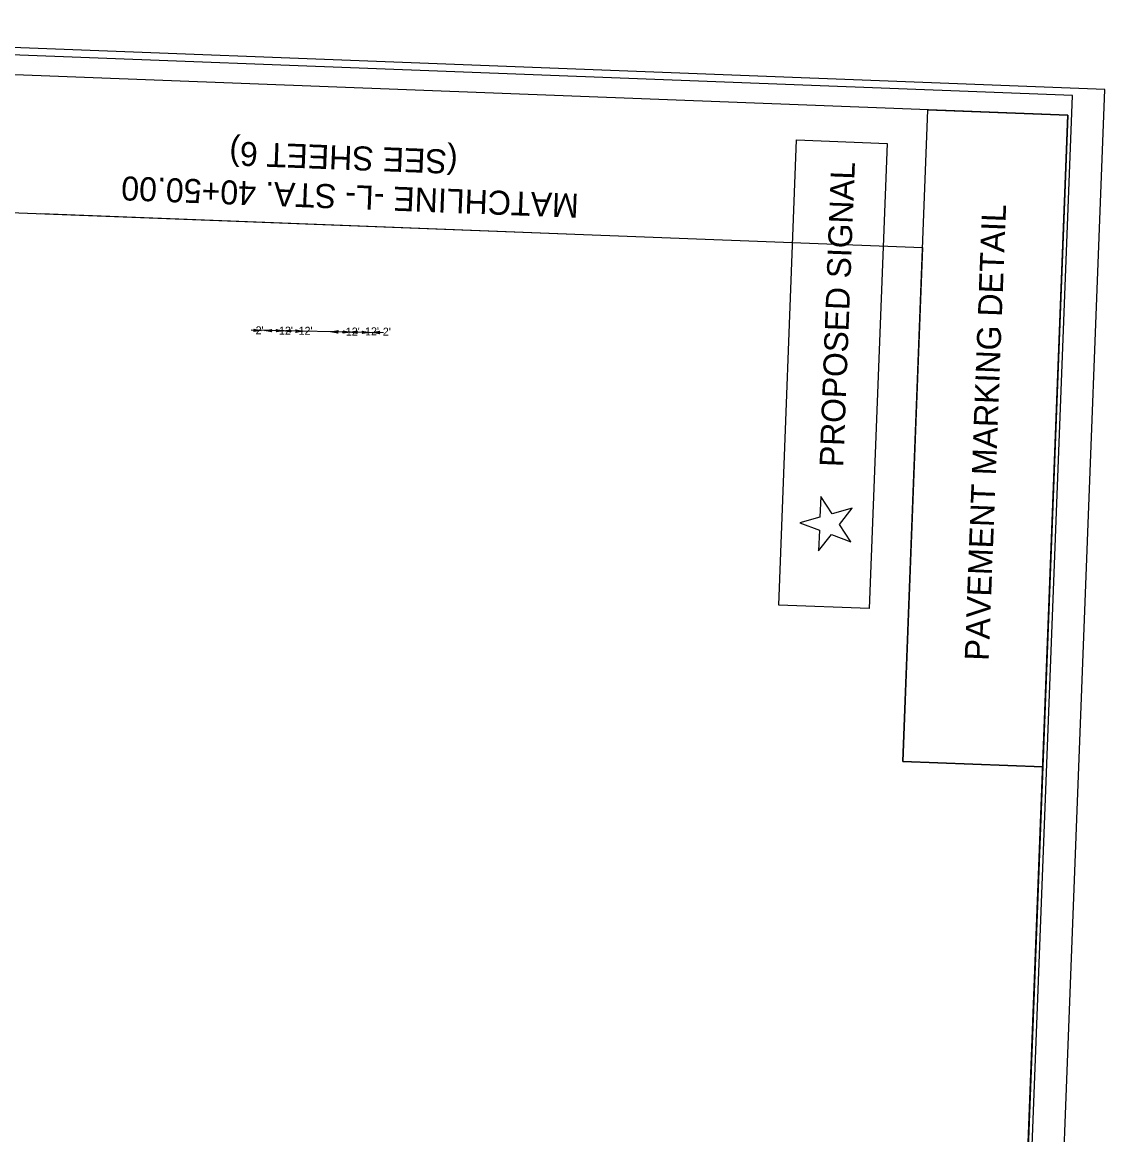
# Model space of a CAD drawing. Extents: x 2097098 to 2098257, y 686470 to 688528.
# Drawn here: x 2097581 to 2098257, y 687499 to 688194 of the extents above; entities that cross this region are included whole.
import ezdxf

# ---------------------------------------------------------------- set-up
doc = ezdxf.new("R2010")
doc.units = 0
for name, color, linetype in [('Default', 7, 'Continuous'), ('Matchline', 7, 'Continuous'), ('Matchline Text', 7, 'Continuous'), ('Sheet Layout Plan Border', 7, 'Continuous'), ('Sheet Plan CELL', 7, 'Continuous'), ('Sheet Plot Border Inside CELL', 7, 'Continuous'), ('Sheet Plot Border Outside CELL', 7, 'Continuous'), ('Text', 7, 'Continuous')]:
    doc.layers.add(name, color=color, linetype=linetype)

msp = doc.modelspace()

# ---------------------------------------------------------------- linework, layer by layer
at = {"layer": 'Default'}
msp.add_line((2097806.64, 688000.26), (2097724.16, 688001.77), dxfattribs=at)
for points in [[(2098053.62, 687830.02), (2098064.77, 688120.69), (2098121.27, 688118.53), (2098110.12, 687827.85)], [(2097725.8, 688002.52), (2097730.28, 688001.66), (2097725.74, 688000.94), (2097726.33, 688001.73)], [(2097736.84, 688000.76), (2097732.36, 688001.62), (2097736.9, 688002.34), (2097736.31, 688001.55)], [(2097739.78, 688002.26), (2097744.26, 688001.4), (2097739.72, 688000.69), (2097740.31, 688001.48)], [(2097748.76, 688000.55), (2097744.27, 688001.4), (2097748.81, 688002.12), (2097748.22, 688001.33)], [(2097751.94, 688002.04), (2097756.42, 688001.18), (2097751.89, 688000.46), (2097752.47, 688001.25)], [(2097778.25, 688000), (2097773.77, 688000.86), (2097778.31, 688001.58), (2097777.72, 688000.79)], [(2097781.44, 688001.47), (2097785.92, 688000.61), (2097781.38, 687999.9), (2097781.97, 688000.68)], [(2097790.25, 687999.78), (2097785.77, 688000.64), (2097790.31, 688001.36), (2097789.72, 688000.57)], [(2097793.43, 688001.25), (2097797.92, 688000.39), (2097793.38, 687999.68), (2097793.97, 688000.46)], [(2097804.25, 687999.53), (2097799.76, 688000.39), (2097804.3, 688001.1), (2097803.71, 688000.31)]]:
    msp.add_lwpolyline(points, close=True, dxfattribs=at)
msp.add_lwpolyline([(2098079.01, 687876.9), (2098078.52, 687863.99), (2098086.5, 687874.15), (2098098.65, 687869.68), (2098091.45, 687880.44), (2098099.44, 687890.61), (2098087, 687887.08), (2098079.81, 687897.82), (2098079.31, 687884.9), (2098066.86, 687881.37), (2098079.01, 687876.9)], dxfattribs=at)
at = {"layer": 'Matchline'}
msp.add_line((2097592.68, 688074.63), (2097942.42, 688061.22), dxfattribs=at)
at = {"layer": 'Sheet Layout Plan Border'}
msp.add_lwpolyline([(2098218.44, 687728.94), (2098179.19, 686705.44), (2097129.59, 686735.95), (2097169.5, 687776.57), (2097171.49, 687828.53), (2097176.8, 687966.96), (2097416.72, 687957.76), (2097421.45, 688081.2), (2098143.33, 688053.51), (2098131.01, 687732.3)], close=True, dxfattribs=at)
at = {"layer": 'Sheet Plan CELL'}
for p, q in [((2098234.06, 688136.14), (2097184.83, 688176.38)), ((2098176.58, 686637.23), (2098234.06, 688136.14))]:
    msp.add_line(p, q, dxfattribs=at)
msp.add_lwpolyline([(2098234.06, 688136.14), (2098218.44, 687728.94), (2098131.01, 687732.3), (2098146.62, 688139.5)], close=True, dxfattribs=at)
at = {"layer": 'Sheet Plot Border Inside CELL'}
msp.add_lwpolyline([(2098173.2, 686483.77), (2098237.04, 688148.49), (2097182.82, 688188.93), (2097118.98, 686524.2)], close=True, dxfattribs=at)
at = {"layer": 'Sheet Plot Border Outside CELL'}
msp.add_lwpolyline([(2098192.69, 686470.01), (2098257.21, 688152.23), (2097163.01, 688194.19), (2097098.5, 686511.97)], close=True, dxfattribs=at)

# ---------------------------------------------------------------- texts
at = {"layer": 'Default'}
msp.add_text('PROPOSED SIGNAL', height=14.8414, rotation=87.8037, dxfattribs=at).set_placement((2098093.89, 687916.1))
at = {"layer": 'Matchline Text'}
for s, p in [('(SEE SHEET 6)', (2097853.26, 688114.34)), ('MATCHLINE -L- STA. 40+50.00', (2097928.97, 688087.04))]:
    msp.add_text(s, height=15, rotation=177.8037, dxfattribs=at).set_placement(p)
at = {"layer": 'Text'}
for s, height, rotation, p in [('PAVEMENT MARKING DETAIL', 15, 87.8037, (2098184.7, 687795.11)), ("2'", 5, 0.22305, (2097726.84, 687999.2)), ("12'", 5, 0.22305, (2097741.44, 687998.99)), ("12'", 5, 0.22305, (2097753.7, 687998.91)), ("12'", 5, 0.22305, (2097783.19, 687998.43)), ("12'", 5, 0.22305, (2097795.19, 687998.56)), ("2'", 5, 0.22305, (2097806.32, 687998.36))]:
    msp.add_text(s, height=height, rotation=rotation, dxfattribs=at).set_placement(p)

doc.saveas('drawing.dxf')
